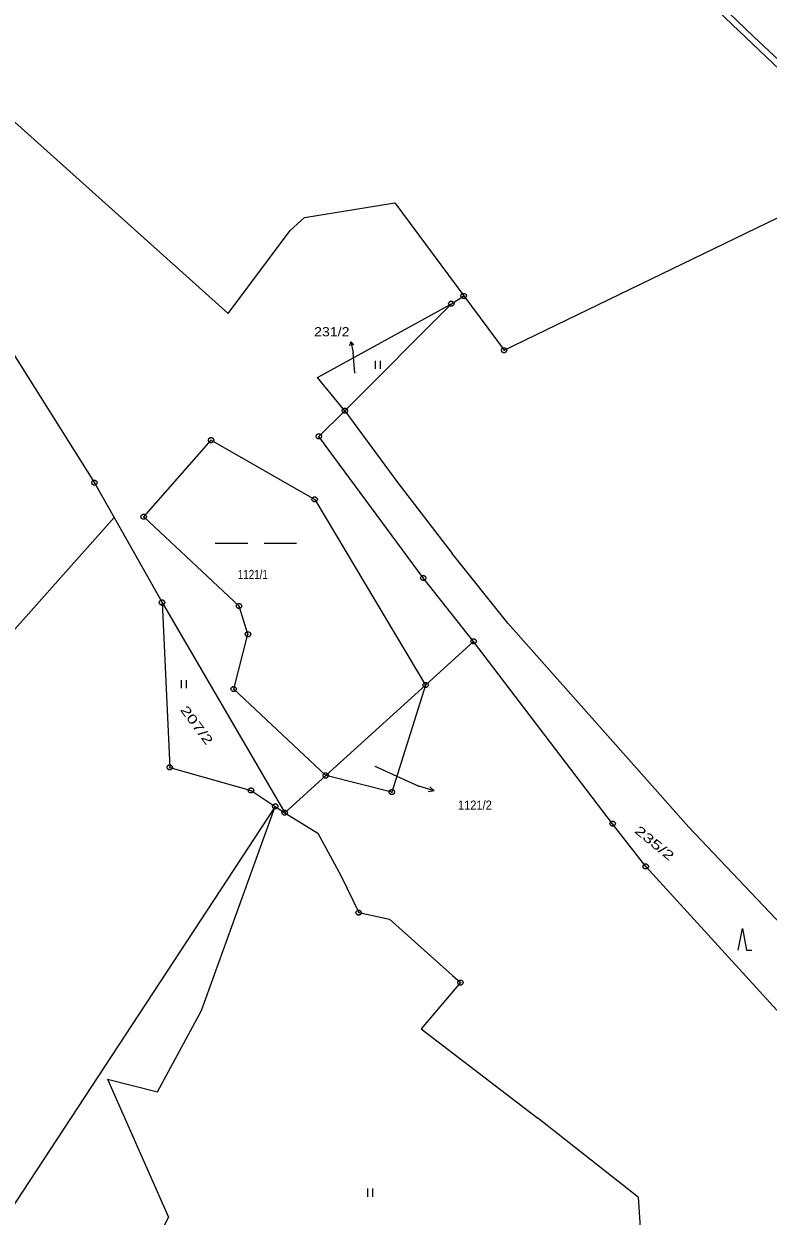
# Model space of a CAD drawing. Extents: x -687390 to -684106, y -954833 to -951648.
# Drawn here: x -686538.6 to -686401.1, y -952593.8 to -952373.7 of the extents above; entities that cross this region are included whole.
import ezdxf
from ezdxf.enums import TextEntityAlignment as Align

# ---------------------------------------------------------------- set-up
doc = ezdxf.new("R2010")
doc.units = 0
doc.header["$LTSCALE"] = 0.68
for name, color, linetype, lineweight in [('1', 7, 'Continuous', 13), ('3', 7, 'Continuous', 13), ('4', 7, 'Continuous', 13), ('7', 7, 'Continuous', 13), ('8', 7, 'Continuous', 13)]:
    doc.layers.add(name, color=color, linetype=linetype, lineweight=lineweight)
doc.layers.add('2', color=7, linetype='Continuous')

msp = doc.modelspace()

# ---------------------------------------------------------------- linework, layer by layer
at = {"layer": '1'}
for p, q in [((-686479.3, -952445.08), (-686469.53, -952458.4)), ((-686469.53, -952458.4), (-686459.49, -952471.42)), ((-686449.19, -952484.28), (-686459.49, -952471.42)), ((-686513.07, -952480.49), (-686490.41, -952519.29)), ((-686490.41, -952519.29), (-686482.83, -952512.43)), ((-686465.21, -952559.19), (-686443.64, -952575.7)), ((-686425.13, -952590.27), (-686443.64, -952575.7)), ((-686425.13, -952590.27), (-686423.68, -952611.6))]:
    msp.add_line(p, q, dxfattribs=at)
for points in [[(-686623.46, -952279.64), (-686624.96, -952282.62), (-686626.61, -952301.13), (-686631.53, -952322.87), (-686641.34, -952351.45), (-686652.22, -952362.81), (-686659.63, -952369.13), (-686648.08, -952374.71), (-686634.56, -952381.48), (-686619.46, -952386.48), (-686599.68, -952383.77), (-686603.98, -952392.18), (-686598.64, -952402.07), (-686585.34, -952406.85), (-686566.31, -952418.36), (-686550.51, -952430.86), (-686541.6, -952432.87), (-686525.56, -952458.37), (-686521.93, -952464.8)], [(-686380.07, -952400.11), (-686419.13, -952362.9), (-686474.9, -952309.94), (-686500.03, -952286.93), (-686550.07, -952353.9), (-686563.44, -952329.54), (-686597.2, -952300.8), (-686623.46, -952279.64)], [(-686631.53, -952322.87), (-686623.89, -952330.65), (-686602.88, -952342.69), (-686584.63, -952360.57), (-686544.5, -952388.07), (-686500.88, -952427.16), (-686489.41, -952411.8), (-686486.74, -952409.41), (-686470.09, -952406.69), (-686457.34, -952423.89)], [(-686455.51, -952487.68), (-686464.82, -952475.96), (-686484.11, -952449.81), (-686479.3, -952445.08), (-686459.63, -952425.34), (-686457.34, -952423.89), (-686449.88, -952433.92), (-686380.07, -952400.11)], [(-686479.3, -952445.08), (-686484.35, -952438.93), (-686459.63, -952425.34)], [(-686578.55, -952523.39), (-686575.97, -952525.47), (-686521.93, -952464.8), (-686513.07, -952480.49)], [(-686513.07, -952480.49), (-686511.64, -952510.94), (-686496.64, -952515.19), (-686492.17, -952518.13)], [(-686391.66, -952547.3), (-686415.73, -952521.94), (-686449.19, -952484.28)], [(-686482.83, -952512.43), (-686464.38, -952495.72), (-686455.51, -952487.68)], [(-686349.52, -952554.62), (-686387.28, -952557.89), (-686399.5, -952555.73), (-686423.73, -952529.22), (-686429.83, -952521.32), (-686455.51, -952487.68)], [(-686492.17, -952518.13), (-686580.4, -952652.47), (-686584.25, -952651.36)], [(-686523.17, -952568.47), (-686513.91, -952570.81), (-686505.76, -952555.78), (-686492.17, -952518.13), (-686490.41, -952519.29)], [(-686490.41, -952519.29), (-686484.29, -952523.07), (-686480.07, -952530.9), (-686476.74, -952537.74), (-686471.04, -952538.96), (-686459.39, -952549.32), (-686457.94, -952550.66), (-686465.21, -952559.19)], [(-686523.17, -952568.47), (-686511.91, -952593.94), (-686536.12, -952640.66)]]:
    msp.add_lwpolyline(points, dxfattribs=at)
msp.add_lwpolyline([(-686504.01, -952450.52), (-686484.87, -952461.45), (-686464.38, -952495.72), (-686470.62, -952515.47), (-686482.83, -952512.43), (-686499.83, -952496.48), (-686497.2, -952486.35), (-686498.85, -952481.14), (-686516.47, -952464.67)], close=True, dxfattribs=at)
at = {"layer": '3'}
for p, q in [((-686473.72, -952435.86), (-686473.72, -952437.36)), ((-686472.72, -952437.36), (-686472.72, -952435.86)), ((-686503.24, -952469.52), (-686497.24, -952469.52)), ((-686494.24, -952469.52), (-686488.24, -952469.52)), ((-686509.53, -952494.82), (-686509.53, -952496.32)), ((-686508.53, -952496.32), (-686508.53, -952494.82)), ((-686475.14, -952588.68), (-686475.14, -952590.18)), ((-686474.14, -952590.18), (-686474.14, -952588.68))]:
    msp.add_line(p, q, dxfattribs=at)
msp.add_lwpolyline([(-686406.62, -952544.66), (-686405.87, -952540.66), (-686405.12, -952544.66), (-686404.12, -952544.66)], dxfattribs=at)
at = {"layer": '4'}
for q in [(-686473.8, -952309.08), (-686378.94, -952399.45)]:
    msp.add_line((-686403.79, -952375.98), q, dxfattribs=at)
at = {"layer": '7'}
for p, q in [((-686478.181, -952432.377), (-686477.75, -952434.34)), ((-686477.46, -952438.13), (-686477.75, -952434.34)), ((-686473.77, -952510.72), (-686465.66, -952514.42)), ((-686462.782, -952515.267), (-686465.66, -952514.42))]:
    msp.add_line(p, q, dxfattribs=at)
for points in [[(-686478.364, -952433.103), (-686478.181, -952432.377), (-686477.71, -952432.959)], [(-686463.6, -952514.505), (-686462.782, -952515.267), (-686463.883, -952515.465)]]:
    msp.add_lwpolyline(points, dxfattribs=at)
at = {"layer": '8'}
for p, q in [((-686457.46, -952423.89), (-686457.22, -952423.89)), ((-686459.75, -952425.34), (-686459.51, -952425.34)), ((-686450, -952433.92), (-686449.76, -952433.92)), ((-686479.42, -952445.08), (-686479.18, -952445.08)), ((-686504.13, -952450.52), (-686503.89, -952450.52)), ((-686484.23, -952449.81), (-686483.99, -952449.81)), ((-686525.68, -952458.37), (-686525.44, -952458.37)), ((-686484.99, -952461.45), (-686484.75, -952461.45)), ((-686516.59, -952464.67), (-686516.35, -952464.67)), ((-686464.94, -952475.96), (-686464.7, -952475.96)), ((-686513.19, -952480.49), (-686512.95, -952480.49)), ((-686498.97, -952481.14), (-686498.73, -952481.14)), ((-686497.32, -952486.35), (-686497.08, -952486.35)), ((-686455.63, -952487.68), (-686455.39, -952487.68)), ((-686499.95, -952496.48), (-686499.71, -952496.48)), ((-686464.5, -952495.72), (-686464.26, -952495.72)), ((-686511.76, -952510.94), (-686511.52, -952510.94)), ((-686482.95, -952512.43), (-686482.71, -952512.43)), ((-686496.76, -952515.19), (-686496.52, -952515.19)), ((-686470.74, -952515.47), (-686470.5, -952515.47)), ((-686492.29, -952518.13), (-686492.05, -952518.13)), ((-686490.53, -952519.29), (-686490.29, -952519.29)), ((-686429.95, -952521.32), (-686429.71, -952521.32)), ((-686423.85, -952529.22), (-686423.61, -952529.22)), ((-686476.86, -952537.74), (-686476.62, -952537.74)), ((-686458.06, -952550.66), (-686457.82, -952550.66))]:
    msp.add_line(p, q, dxfattribs=at)
for points in [[(-686459.48, -952424.86), (-686459.23, -952425.04), (-686459.13, -952425.33), (-686459.23, -952425.62), (-686459.48, -952425.8), (-686459.79, -952425.8), (-686460.04, -952425.62), (-686460.14, -952425.33), (-686460.04, -952425.04), (-686459.79, -952424.86)], [(-686457.19, -952423.41), (-686456.94, -952423.59), (-686456.84, -952423.88), (-686456.94, -952424.17), (-686457.19, -952424.35), (-686457.5, -952424.35), (-686457.75, -952424.17), (-686457.85, -952423.88), (-686457.75, -952423.59), (-686457.5, -952423.41)], [(-686449.73, -952433.44), (-686449.48, -952433.62), (-686449.38, -952433.91), (-686449.48, -952434.2), (-686449.73, -952434.38), (-686450.04, -952434.38), (-686450.29, -952434.2), (-686450.39, -952433.91), (-686450.29, -952433.62), (-686450.04, -952433.44)], [(-686479.15, -952444.6), (-686478.9, -952444.78), (-686478.8, -952445.07), (-686478.9, -952445.36), (-686479.15, -952445.54), (-686479.46, -952445.54), (-686479.71, -952445.36), (-686479.81, -952445.07), (-686479.71, -952444.78), (-686479.46, -952444.6)], [(-686483.96, -952449.33), (-686483.71, -952449.51), (-686483.61, -952449.8), (-686483.71, -952450.09), (-686483.96, -952450.27), (-686484.27, -952450.27), (-686484.52, -952450.09), (-686484.62, -952449.8), (-686484.52, -952449.51), (-686484.27, -952449.33)], [(-686503.86, -952450.04), (-686503.61, -952450.22), (-686503.51, -952450.51), (-686503.61, -952450.8), (-686503.86, -952450.98), (-686504.17, -952450.98), (-686504.42, -952450.8), (-686504.52, -952450.51), (-686504.42, -952450.22), (-686504.17, -952450.04)], [(-686525.41, -952457.89), (-686525.16, -952458.07), (-686525.06, -952458.36), (-686525.16, -952458.65), (-686525.41, -952458.83), (-686525.72, -952458.83), (-686525.97, -952458.65), (-686526.07, -952458.36), (-686525.97, -952458.07), (-686525.72, -952457.89)], [(-686484.72, -952460.97), (-686484.47, -952461.15), (-686484.37, -952461.44), (-686484.47, -952461.73), (-686484.72, -952461.91), (-686485.03, -952461.91), (-686485.28, -952461.73), (-686485.38, -952461.44), (-686485.28, -952461.15), (-686485.03, -952460.97)], [(-686516.32, -952464.19), (-686516.07, -952464.37), (-686515.97, -952464.66), (-686516.07, -952464.95), (-686516.32, -952465.13), (-686516.63, -952465.13), (-686516.88, -952464.95), (-686516.98, -952464.66), (-686516.88, -952464.37), (-686516.63, -952464.19)], [(-686464.67, -952475.48), (-686464.42, -952475.66), (-686464.32, -952475.95), (-686464.42, -952476.24), (-686464.67, -952476.42), (-686464.98, -952476.42), (-686465.23, -952476.24), (-686465.33, -952475.95), (-686465.23, -952475.66), (-686464.98, -952475.48)], [(-686512.92, -952480.01), (-686512.67, -952480.19), (-686512.57, -952480.48), (-686512.67, -952480.77), (-686512.92, -952480.95), (-686513.23, -952480.95), (-686513.48, -952480.77), (-686513.58, -952480.48), (-686513.48, -952480.19), (-686513.23, -952480.01)], [(-686498.7, -952480.66), (-686498.45, -952480.84), (-686498.35, -952481.13), (-686498.45, -952481.42), (-686498.7, -952481.6), (-686499.01, -952481.6), (-686499.26, -952481.42), (-686499.36, -952481.13), (-686499.26, -952480.84), (-686499.01, -952480.66)], [(-686497.05, -952485.87), (-686496.8, -952486.05), (-686496.7, -952486.34), (-686496.8, -952486.63), (-686497.05, -952486.81), (-686497.36, -952486.81), (-686497.61, -952486.63), (-686497.71, -952486.34), (-686497.61, -952486.05), (-686497.36, -952485.87)], [(-686455.36, -952487.2), (-686455.11, -952487.38), (-686455.01, -952487.67), (-686455.11, -952487.96), (-686455.36, -952488.14), (-686455.67, -952488.14), (-686455.92, -952487.96), (-686456.02, -952487.67), (-686455.92, -952487.38), (-686455.67, -952487.2)], [(-686464.23, -952495.24), (-686463.98, -952495.42), (-686463.88, -952495.71), (-686463.98, -952496), (-686464.23, -952496.18), (-686464.54, -952496.18), (-686464.79, -952496), (-686464.89, -952495.71), (-686464.79, -952495.42), (-686464.54, -952495.24)], [(-686499.68, -952496), (-686499.43, -952496.18), (-686499.33, -952496.47), (-686499.43, -952496.76), (-686499.68, -952496.94), (-686499.99, -952496.94), (-686500.24, -952496.76), (-686500.34, -952496.47), (-686500.24, -952496.18), (-686499.99, -952496)], [(-686511.49, -952510.46), (-686511.24, -952510.64), (-686511.14, -952510.93), (-686511.24, -952511.22), (-686511.49, -952511.4), (-686511.8, -952511.4), (-686512.05, -952511.22), (-686512.15, -952510.93), (-686512.05, -952510.64), (-686511.8, -952510.46)], [(-686482.68, -952511.95), (-686482.43, -952512.13), (-686482.33, -952512.42), (-686482.43, -952512.71), (-686482.68, -952512.89), (-686482.99, -952512.89), (-686483.24, -952512.71), (-686483.34, -952512.42), (-686483.24, -952512.13), (-686482.99, -952511.95)], [(-686496.49, -952514.71), (-686496.24, -952514.89), (-686496.14, -952515.18), (-686496.24, -952515.47), (-686496.49, -952515.65), (-686496.8, -952515.65), (-686497.05, -952515.47), (-686497.15, -952515.18), (-686497.05, -952514.89), (-686496.8, -952514.71)], [(-686470.47, -952514.99), (-686470.22, -952515.17), (-686470.12, -952515.46), (-686470.22, -952515.75), (-686470.47, -952515.93), (-686470.78, -952515.93), (-686471.03, -952515.75), (-686471.13, -952515.46), (-686471.03, -952515.17), (-686470.78, -952514.99)], [(-686492.02, -952517.65), (-686491.77, -952517.83), (-686491.67, -952518.12), (-686491.77, -952518.41), (-686492.02, -952518.59), (-686492.33, -952518.59), (-686492.58, -952518.41), (-686492.68, -952518.12), (-686492.58, -952517.83), (-686492.33, -952517.65)], [(-686490.26, -952518.81), (-686490.01, -952518.99), (-686489.91, -952519.28), (-686490.01, -952519.57), (-686490.26, -952519.75), (-686490.57, -952519.75), (-686490.82, -952519.57), (-686490.92, -952519.28), (-686490.82, -952518.99), (-686490.57, -952518.81)], [(-686429.68, -952520.84), (-686429.43, -952521.02), (-686429.33, -952521.31), (-686429.43, -952521.6), (-686429.68, -952521.78), (-686429.99, -952521.78), (-686430.24, -952521.6), (-686430.34, -952521.31), (-686430.24, -952521.02), (-686429.99, -952520.84)], [(-686423.58, -952528.74), (-686423.33, -952528.92), (-686423.23, -952529.21), (-686423.33, -952529.5), (-686423.58, -952529.68), (-686423.89, -952529.68), (-686424.14, -952529.5), (-686424.24, -952529.21), (-686424.14, -952528.92), (-686423.89, -952528.74)], [(-686476.59, -952537.26), (-686476.34, -952537.44), (-686476.24, -952537.73), (-686476.34, -952538.02), (-686476.59, -952538.2), (-686476.9, -952538.2), (-686477.15, -952538.02), (-686477.25, -952537.73), (-686477.15, -952537.44), (-686476.9, -952537.26)], [(-686457.79, -952550.18), (-686457.54, -952550.36), (-686457.44, -952550.65), (-686457.54, -952550.94), (-686457.79, -952551.12), (-686458.1, -952551.12), (-686458.35, -952550.94), (-686458.45, -952550.65), (-686458.35, -952550.36), (-686458.1, -952550.18)]]:
    msp.add_lwpolyline(points, close=True, dxfattribs=at)

# ---------------------------------------------------------------- texts
at = {"layer": '2'}
for s, height, width, p in [('231/2', 0.1, 1.15, (-686477.432, -952438.13)), ('1121/1', 1.7, 0.8, (-686499.085, -952476.16)), ('1121/2', 0.1, 0.9, (-686473.724, -952510.72))]:
    msp.add_text(s, height=height, dxfattribs=dict(at, width=width)).set_placement(p)
for s, rotation, width, p in [('207/2', 306.647, 1.45, (-686509.807, -952500.321)), ('235/2', 320.627, 1.5, (-686425.933, -952522.851))]:
    msp.add_text(s, height=1.7, rotation=rotation, dxfattribs=dict(at, width=width)).set_placement(p)
at = {"layer": '7', "width": 1.15}
msp.add_text('231/2', height=1.7, dxfattribs=at).set_placement((-686478.446, -952431.35), align=Align.RIGHT)
at = {"layer": '7', "width": 0.9}
msp.add_text('1121/2', height=1.7, dxfattribs=at).set_placement((-686458.415, -952518.75))

doc.saveas('drawing.dxf')
